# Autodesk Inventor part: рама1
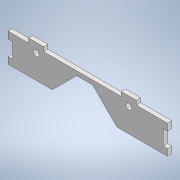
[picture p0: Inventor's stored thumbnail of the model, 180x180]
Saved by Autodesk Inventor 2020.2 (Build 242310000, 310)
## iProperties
Created: 2020-04
Part Number: рама1
Material: Типовые
Document SubType Name: Modeling
Designer: Алексей
Density: 1 g/cm^3
Appearance: По умолчанию
Author: Алексей
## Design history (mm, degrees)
sketch "Эскиз1"
  geometry: L1 (0, 0)-(14, 0) reference; L2 (14, 0)-(14, 4) reference; L3 (0, 4)-(14, 4) reference; L4 (0, 0)-(0, 4) reference; L5 (-86, 0)-(-72, 0) reference; L6 (-72, 0)-(-72, 4) reference; L7 (-86, 4)-(-72, 4) reference; L8 (-86, 0)-(-86, 4) reference; L9 (43, -20)-(43, -26.586) reference; L10 (-105, -36)-(-105, -23) reference; L11 (-105, -20)-(-105, -26.625); L12 (-105, -26.625)-(43, -26.625); L13 (43, -26.625)-(43, -20); L14 (43, -20)-(-105, -20); L15 (-105, -20)-(-105, 0); L16 (-105, 0)-(43, 0); L17 (43, 0)-(43, -20); A1 r 20 centre (7, -2.625) between (-13, -2.625) and (27, -2.625) reference; 14 further points
  constraints: 14 end point, 3 collinear, 3 parallel, 2 horizontal, 1 perpendicular, 1 vertical, 3 other
  dimensions: "d13" = 24 distance from line of L12 A1.centre
extrude "Выдавливание1" new body sketch "Эскиз1" distance "d0" = 4; taper "d1" = 0 deg
sketch "Эскиз2"
  geometry: L1 (0, 0)-(14, 0) reference; L2 (-86, 0)-(-72, 0) reference; L3 (-72, 4)-(-86, 4) reference; C1 r 2.75 at (7, -3); C2 r 2.75 at (-79, -3)
  constraints: 2 centre point, 1 horizontal alignment
  dimensions: "d2" = 5.5 diameter of C1; "d3" = 5.5 diameter of C2; "d20" = 7 distance from line of C2.centre L3
extrude "Выдавливание2" cut sketch "Эскиз2" extent not by distance; stored distance "d4" = 0; taper "d5" = 0 deg
sketch "Эскиз3"
  geometry: L1 (-105, -26.625)-(43, -26.625) reference; L2 (-4, -26.625)-(-26.625, -4); L3 (-26.625, -4)-(-41.375, -4); L4 (-41.375, -4)-(-64, -26.625); L5 (47, -20)-(47, -26.586) reference; L6 (47, -20)-(43, -20) reference; L7 (43, -20)-(43, -6) reference; L8 (43, -6)-(47, -6) reference; L9 (47, 4)-(47, -6) reference; L10 (27, 4)-(47, 4) reference; L11 (27, -2.625)-(27, 4) reference; L12 (-13, 4)-(-13, -2.625) reference; L13 (-29, 4)-(-13, 4) reference; L14 (-29, 4)-(-29, 0) reference; L15 (-29, 0)-(-43, 0) reference; L16 (-43, 0)-(-43, 4) reference; L17 (-59, 4)-(-43, 4) reference; L18 (-59, -2.625)-(-59, 4) reference; L19 (-99, 4)-(-99, -2.625) reference; L20 (-109, 4)-(-99, 4) reference; L21 (-109, -9)-(-109, 4) reference; L22 (-109, -9)-(-105, -9) reference; L23 (-105, -9)-(-105, -23) reference; L24 (-105, -23)-(-109, -23) reference; L25 (-109, -36)-(-109, -23) reference; L26 (-101.105, -38.718)-(-109, -36) reference; L27 (-98, -43.5)-(-101.105, -38.718) reference; L28 (-91.719, -44.093)-(-98, -43.5) reference; L29 (-91.719, -44.093)-(-91.343, -40.11) reference; L30 (-91.343, -40.11)-(-77.405, -41.425) reference; L31 (-77.405, -41.425)-(-77.781, -45.407) reference; L32 (-71.5, -46)-(-77.781, -45.407) reference; L33 (-65.8, -35.88)-(-71.5, -46) reference; L34 (-56.5, -33.58)-(-65.8, -35.88) reference; L35 (-12.265, -46.736)-(-12.1, -39.938) reference; L36 (-20.694, -65.328)-(-12.265, -46.736) reference; L37 (-14.694, -66)-(-20.694, -65.328) reference; L38 (-9.493, -57.476)-(-14.694, -66) reference; L39 (-9.493, -57.476)-(-12.908, -55.392) reference; L40 (-12.908, -55.392)-(-5.616, -43.441) reference; L41 (-5.616, -43.441)-(-2.201, -45.524) reference; L42 (3, -37)-(-2.201, -45.524) reference; L43 (18.087, -34.6)-(3, -37) reference; L44 (18.087, -34.6)-(17.458, -30.649) reference; L45 (17.458, -30.649)-(31.285, -28.45) reference; L46 (31.285, -28.45)-(31.913, -32.4) reference; L47 (43.628, -30.536)-(31.913, -32.4) reference; L48 (-56.5, -33.58)-(-46.1, -15.152) reference; L49 (-46.1, -15.152)-(-41.529, -10.657) reference; L50 (-41.529, -10.657)-(-25.774, -10.657) reference; L51 (-25.774, -10.657)-(-12.1, -24.562) reference; L52 (-12.1, -24.562)-(-12.1, -39.938) reference; A1 r 4 centre (43, -26.586) between (43.628, -30.536) and (47, -26.586) reference; A2 r 20 centre (7, -2.625) between (-13, -2.625) and (27, -2.625) reference; A3 r 20 centre (-79, -2.625) between (-99, -2.625) and (-59, -2.625) reference; 4 further points; 1 other entity
  constraints: 6 end point, 2 point on line, 1 parallel, 1 other
  dimensions: "d6" = 4 distance of the line from the sketch origin of L3; "d7" = 135 deg angle of L3 L2; "d8" = 135 deg angle of L4 L3
extrude "Выдавливание3" cut sketch "Эскиз3" extent not by distance; stored distance "d11" = 0; taper "d12" = 0 deg
sketch "Эскиз4"
  geometry: L1 (101, -6.313)-(105, -6.313); L2 (105, -6.313)-(105, -20.313); L3 (105, -20.313)-(101, -20.313); L4 (101, -20.313)-(101, -6.313); L5 (-43, -6.312)-(-39, -6.312); L6 (-39, -6.312)-(-39, -20.312); L7 (-39, -20.312)-(-43, -20.312); L8 (-43, -20.312)-(-43, -6.312); L9 (4, -26.625)-(26.625, -4) reference; L10 (26.625, -4)-(41.375, -4) reference; L11 (41.375, -4)-(64, -26.625) reference; L12 (105, -26.625)-(64, -26.625) reference; L13 (105, 0)-(105, -26.625) reference; L14 (86, 0)-(105, 0) reference; L15 (86, 4)-(86, 0) reference; L16 (72, 4)-(86, 4) reference; L17 (72, 0)-(72, 4) reference; L18 (0, 0)-(72, 0) reference; L19 (0, 4)-(0, 0) reference; L20 (-14, 4)-(0, 4) reference; L21 (-14, 0)-(-14, 4) reference; L22 (-43, 0)-(-14, 0) reference; L23 (-43, -26.625)-(-43, 0) reference; L24 (4, -26.625)-(-43, -26.625) reference; C1 r 2.75 at (-7, -3) reference; C2 r 2.75 at (79, -3) reference; 4 further points
  constraints: 16 end point, 4 midpoint, 2 parallel, 1 perpendicular
  dimensions: "d15" = 14 distance of L2.end L1.end; "d16" = 4 distance of L6.end L7.end; "d17" = 14 distance of L5.end L6.end; "d21" = 4 distance of L2.end L3.end
extrude "Выдавливание4" cut sketch "Эскиз4" extent not by distance; stored distance "d18" = 0; taper "d19" = 0 deg
node "Твердое тело1"
node "Ссылка1"
node "Ссылка2"
node "Ссылка3"
node "Ссылка4"
node "Ссылка5"
node "Ссылка9"
node "Ссылка10"
node "Ссылка11"
node "Спроецированная петля1"
feature "Машинка.iam"
